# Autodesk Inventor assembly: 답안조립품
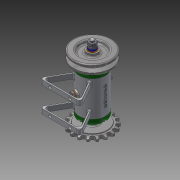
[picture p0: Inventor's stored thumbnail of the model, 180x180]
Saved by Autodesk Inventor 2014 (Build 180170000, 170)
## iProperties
Created: 2016-03
Part Number: 답안조립품
Document SubType Name: Assembly
Designer: 406-0077
Author: 406-0077
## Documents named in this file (16)
- C:\Users\406-0077\Desktop\460307V1015\답안조립품.iam
- C:\Users\406-0077\Desktop\460307V1015\1.본체.ipt
- C:\Users\406-0077\Desktop\460307V1015\커버.ipt
- C:\Users\406-0077\Desktop\460307V1015\베어링 15 x 32 x 9.ipt
- C:\Users\406-0077\Desktop\460307V1015\축.ipt
- C:\Users\406-0077\Desktop\460307V1015\키 3 x 3 x 12.ipt
- C:\Users\406-0077\Desktop\460307V1015\오일 실 15 25 7.ipt
- C:\Users\406-0077\Desktop\460307V1015\V벨트풀리.ipt
- C:\Users\406-0077\Desktop\460307V1015\스프로킷.ipt
- C:\Users\406-0077\Desktop\460307V1015\너트 M 8.ipt
- C:\Users\406-0077\Desktop\460307V1015\스프링와셔 8.ipt
- C:\Users\406-0077\Desktop\460307V1015\와셔 8x17.ipt
- C:\Users\406-0077\Desktop\460307V1015\니플 M 6 x 0.75.ipt
- C:\Users\406-0077\Desktop\460307V1015\볼트 M 6 x 8.ipt
- C:\Users\406-0077\Desktop\460307V1015\와셔 6x11.5.ipt
- C:\Users\406-0077\Desktop\460307V1015\볼트 M4 x 12.ipt
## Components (12 placed, 4 different names)
1. 1.본체:1
2. KS B 2023 6002 - 15 x 32 x 9:1
3. KS B 2023 6002 - 15 x 32 x 9:2
4. V벨트풀리:1 — 각도:3
5. ISO 4762 M4 x 12:5
6. ISO 4762 M4 x 12:6
7. ISO 4762 M4 x 12:7
8. ISO 4762 M4 x 12:8
9. ISO 4762 M4 x 12:9
10. ISO 4762 M4 x 12:10
11. ISO 4762 M4 x 12:11
12. ISO 4762 M4 x 12:12
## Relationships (1: Angle 1)
- 각도:3 [Angle]: V벨트풀리:1
